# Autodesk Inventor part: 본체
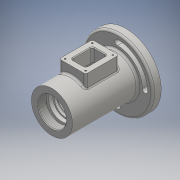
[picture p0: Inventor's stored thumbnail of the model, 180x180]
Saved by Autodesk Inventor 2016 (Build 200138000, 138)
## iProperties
Created: 2017-05
Part Number: 본체
Material: 일반
Document SubType Name: Modeling
Designer: USER
Density: 1 g/cm^3
Appearance: 기본값
Author: USER
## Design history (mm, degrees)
sketch "스케치1"
  geometry: C1 r 53 at (0, 0); 1 further point
  constraints: 1 centre point, 1 coincident
  dimensions: "d0" = 106 diameter of C1
extrude "돌출1" new body sketch "스케치1" distance "d1" = 13; taper "d2" = 0 deg
sketch "스케치2"
  geometry: C1 r 31 at (0, 0); 1 further point
  constraints: 1 centre point, 1 coincident
  dimensions: "d3" = 62 diameter of C1
extrude "돌출2" join sketch "스케치2" distance "d4" = 3; taper "d5" = 0 deg
sketch "스케치3"
  geometry: C1 r 31 at (0, 0); 1 further point
  constraints: 1 centre point, 1 coincident
  dimensions: "d6" = 62 diameter of C1
extrude "돌출3" join sketch "스케치3" distance "d7" = 99; taper "d8" = 0 deg
sketch "스케치4"
  geometry: L1 (-138.323, 0)-(35.373, 0); L2 (-99, 31)-(-99, -31) reference; L3 (-99, 0)-(-99, 21); L4 (-99, 21)-(-87, 21); L5 (-87, 21)-(-87, 24); L6 (-87, 24)-(-84, 24); L7 (-84, 24)-(-84, 20); L8 (-84, 20)-(-78, 20); L9 (-78, 20)-(-78, 17.5); L10 (-78, 17.5)-(-74.75, 17.5); L11 (-74.75, 17.5)-(-74.75, 18.5); L12 (-74.75, 18.5)-(-73, 18.5); L13 (-73, 18.5)-(-73, 17.5); L14 (-73, 17.5)-(-62, 17.5); L15 (-62, 17.5)-(-62, 26); L16 (-62, 26)-(-24, 26); L17 (-24, 26)-(-24, 17.5); L18 (-24, 17.5)-(-13, 17.5); L19 (-13, 17.5)-(-13, 16.5); L20 (-13, 16.5)-(-11, 16.5); L21 (-8, 13.5)-(-8, 10); L22 (-8, 10)-(-5.3, 10); L23 (-5.3, 10)-(-5.3, 12.5); L24 (-5.3, 12.5)-(2, 12.5); L25 (2, 12.5)-(2, 16); L26 (2, 16)-(16, 22); L27 (16, -31)-(16, 31) reference; L28 (0, 31)-(-99, 31) reference; L29 (16, 22)-(16, 0); L30 (-99, 0)-(16, 0); A1 r 3 centre (-11, 13.5) between (-8, 13.5) and (-11, 16.5); 1 further point
  constraints: 54 end point, 16 perpendicular, 4 horizontal, 3 vertical, 2 midpoint, 2 point on circle, 2 point on line, 2 tangent, 1 centre point, 1 collinear, 1 horizontal alignment
  dimensions: "d9" = 42 diameter of L4 L1; "d10" = 48 diameter of L6 L1; "d11" = 3 distance of L5.end L6.end; "d12" = 40 diameter of L8 L1; "d13" = 12 distance of L3.end L4.end; "d14" = 21 distance between parallel lines of L2 L9; "d15" = 35 diameter of L10 L1; "d16" = 37 diameter of L12 L1; "d17" = 1.75 distance of L11.end L12.end; "d18" = 26 distance between parallel lines of L3 L13; "d19" = 11 distance of L13.end L14.end; "d20" = 35 diameter of L14 L1; "d21" = 38 distance of L15.end L16.end; "d22" = 52 diameter of L16 L1; "d23" = 11 distance of L17.end L18.end; "d24" = 35 diameter of L18 L1; "d25" = 3 radius of A1; "d26" = 33 diameter of L20 L1; "d27" = 2.7 distance of L21.end L22.end; "d28" = 20 diameter of L22 L1; "d29" = 25 diameter of L24 L1; "d30" = 7.3 distance of L23.end L24.end; "d31" = 32 diameter of L25.end L1; "d32" = 44 diameter of L26.end L1; "d33" = 14 distance from line of L25 L26.end
revolve "회전1" sketch "스케치4" stored, may be unused: angle "d34" = 90 deg
fillet "모깎기2" dims "d36" = 0.3
chamfer "모따기1" distance "d37" = 1; stored, may be unused: second distance "d38" = 2, angle "d39" = 45 deg
fillet "모깎기3" dims "d43" = 0.3
chamfer "모따기4" distance "d47" = 0.7; stored, may be unused: second distance "d48" = 2, angle "d49" = 30 deg
fillet "모깎기4" dims "d50" = 3
sketch "스케치8"
  geometry: A1 r 41.5 centre (0, 0) between (0, 41.5) and (-41.5, 0); A2 r 45.5 centre (0, 0) between (0, 45.5) and (-45.5, 0); A3 r 37.5 centre (0, 0) between (0, 37.5) and (-37.5, 0); A4 r 4 centre (0, 41.5) between (0, 37.5) and (0, 45.5); A5 r 4 centre (-41.5, 0) between (-45.5, 0) and (-37.5, 0); A6 r 41.5 centre (0, 0) between (0, -41.5) and (41.5, 0); A7 r 45.5 centre (0, 0) between (0, -45.5) and (45.5, 0); A8 r 37.5 centre (0, 0) between (0, -37.5) and (37.5, 0); A9 r 4 centre (0, -41.5) between (0, -37.5) and (0, -45.5); A10 r 4 centre (41.5, 0) between (45.5, 0) and (37.5, 0); 1 further point
  constraints: 20 point on circle, 10 centre point, 8 tangent, 2 coincident, 2 horizontal alignment, 2 vertical alignment
  dimensions: "d51" = 45.5 radius of A2; "d53" = 41.5 radius of A1; "d54" = 45.5 radius of A7; "d55" = 41.5 radius of A6
extrude "돌출4" cut sketch "스케치8" stored distance "d56" = 99; taper "d57" = 0 deg
node "작업 평면1"
sketch "스케치9"
  geometry: L1 (-20, -18)-(20, -18); L2 (20, -18)-(20, -68); L3 (20, -68)-(-20, -68); L4 (-20, -68)-(-20, -18); L5 (-20, -43)-(0, -43); L6 (-31, -99)-(31, -99) reference; 2 further points
  constraints: 10 end point, 2 horizontal, 2 midpoint, 2 parallel, 1 perpendicular, 1 vertical alignment
  dimensions: "d59" = 50 distance of L1.end L2.end; "d60" = 40 distance of L1.start L1.end; "d61" = 56 distance between parallel lines of L6 L5
extrude "돌출5" join sketch "스케치9" stored distance "d62" = 99; taper "d63" = 0 deg
sketch "스케치10"
  geometry: L1 (-20, -18)-(20, -18) reference; L2 (-20, -68)-(-20, -18) reference; L3 (20, -68)-(-20, -68) reference; L4 (20, -18)-(20, -68) reference; L5 (-11, -27)-(11, -27); L6 (11, -27)-(11, -59); L7 (11, -59)-(-11, -59); L8 (-11, -59)-(-11, -27); 4 further points
  constraints: 8 end point, 3 midpoint, 2 parallel, 1 horizontal, 1 horizontal alignment, 1 perpendicular, 1 vertical alignment
  dimensions: "d64" = 32 distance of L5.end L6.end; "d65" = 22 distance of L6.end L7.end
extrude "돌출6" cut sketch "스케치10" stored distance "d66" = 99; taper "d67" = 0 deg
fillet "모깎기5" dims "d68" = 3
fillet "모깎기6" dims "d69" = 3
fillet "모깎기7" dims "d73" = 3
chamfer "모따기6" distance "d74" = 1; stored, may be unused: second distance "d75" = 2, angle "d76" = 30 deg
fillet "모깎기8" dims "d77" = 3
feature "스레드1" dims "d78" = 10, "d79" = 0
sketch "스케치11"
  geometry: L1 (-20, -65)-(-20, -21) reference; L2 (-20, -65)-(-20, -21) reference; L3 (-20, -43)-(20, -43); L4 (20, -21)-(20, -65) reference; L5 (17, -68)-(-17, -68) reference; L6 (0, -68)-(0, -18); L7 (17, -18)-(-17, -18) reference; 5 further points
  constraints: 4 end point, 4 midpoint, 2 horizontal alignment, 2 vertical alignment
  dimensions: "d80" = 41 distance of point (15.5, -63.5) point (15.5, -22.5); "d81" = 31 distance of point (15.5, -63.5) point (-15.5, -63.5); "d82" = 15.5 distance from line of point (-15.5, -63.5) L6; "d83" = 20.5 distance from line of point (-15.5, -22.5) L3
hole "구멍1" sketch "스케치11" at (-15.5, -22.5), (15.5, -22.5), (15.5, -63.5), (-15.5, -63.5) diameter "d84" = 2.459; stored, may be unused: countersink angle "d88" = 90 deg, drill point angle "d90" = 118 deg; dims "d85" = 6, "d86" = 4, "d87" = 2, "d89" = 8
node "솔리드1"
node "투영된 루프2"
other parameters: "d58" = 44
